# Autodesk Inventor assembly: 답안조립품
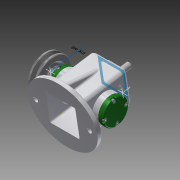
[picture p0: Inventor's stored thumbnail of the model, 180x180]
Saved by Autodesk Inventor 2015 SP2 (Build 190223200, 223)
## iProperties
Created: 2017-07
Part Number: 답안조립품
Document SubType Name: Assembly
Designer: Admin
Author: Admin
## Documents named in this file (16)
- C:\Users\Admin\Desktop\470707V1008\답안조립품.iam
- C:\Users\Admin\Desktop\470707V1008\본체.ipt
- C:\Users\Admin\Desktop\470707V1008\앞커버.ipt
- C:\Users\Admin\Desktop\470707V1008\뒤커버.ipt
- C:\Users\Admin\Desktop\470707V1008\베어링 12 x 32 x 10.ipt
- C:\Users\Admin\Desktop\470707V1008\오일실 12 25 7.ipt
- C:\Users\Admin\Desktop\470707V1008\편심축.ipt
- C:\Users\Admin\Desktop\470707V1008\V벨트풀리.ipt
- C:\Users\Admin\Desktop\470707V1008\키 4 x 4 x 10.ipt
- C:\Users\Admin\Desktop\470707V1008\슬라이드.ipt
- C:\Users\Admin\Desktop\470707V1008\부시.ipt
- C:\Users\Admin\Desktop\470707V1008\링크.ipt
- C:\Users\Admin\Desktop\470707V1008\핀 5 x 18.ipt
- C:\Users\Admin\Desktop\470707V1008\고정핀 1.2 x  8.ipt
- C:\Users\Admin\Desktop\470707V1008\멈춤나사 M3x8.ipt
- C:\Users\Admin\Desktop\470707V1008\볼트 M4 x 12.ipt
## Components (3 placed, 3 different names)
1. V벨트풀리:1 — 각도:1
2. 핀 5 x 18:1
3. 고정핀 1.2 x  8:1
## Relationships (1: Angle 1)
- 각도:1 [Angle]: V벨트풀리:1
